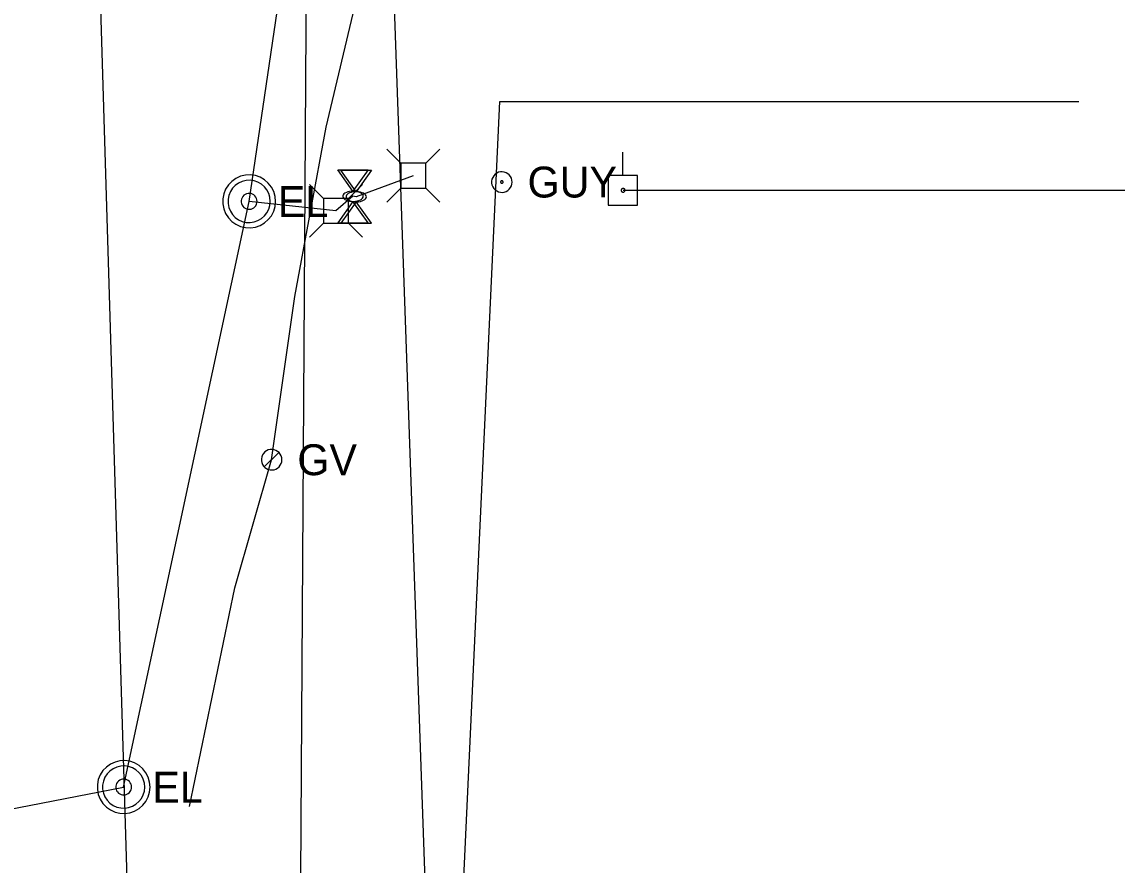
# Model space of a CAD drawing. Extents: x 596028 to 606371, y 330010 to 403088.
# Drawn here: x 605009.9 to 605146.4, y 331475.9 to 331581 of the extents above; entities that cross this region are included whole.
import ezdxf

# ---------------------------------------------------------------- set-up
doc = ezdxf.new("R2010")
doc.units = 0
for name, color, linetype in [('E_UTL_E', 7, 'Continuous'), ('E_UTL_E_Bold', 7, 'Continuous'), ('E_UTL_E_UG', 7, 'Continuous'), ('E_UTL_EGuyWire', 7, 'Continuous'), ('E_UTL_EPowerPole', 7, 'Continuous'), ('E_UTL_G', 7, 'Continuous'), ('E_UTL_G_UG', 7, 'Continuous'), ('E_UTL_Overhead', 7, 'Continuous'), ('E_UTL_SAN_UG', 7, 'Continuous'), ('E_UTL_SAN_UG_MMSD', 7, 'Continuous'), ('E_UTL_W_UG', 7, 'Continuous')]:
    doc.layers.add(name, color=color, linetype=linetype)

msp = doc.modelspace()

# ---------------------------------------------------------------- linework, layer by layer
at = {"layer": 'E_UTL_E'}
for points in [[(605057.12, 331563.38), (605055.37, 331565.13)], [(605060.22, 331563.38), (605061.97, 331565.13)], [(605060.22, 331563.38), (605057.12, 331563.38)], [(605057.12, 331563.38), (605057.12, 331560.28)], [(605060.22, 331560.28), (605060.22, 331563.38)], [(605041.5, 331558.64), (605041.44, 331559.26), (605041.27, 331559.86), (605040.98, 331560.42), (605040.59, 331560.92), (605040.12, 331561.33), (605039.57, 331561.64), (605038.98, 331561.85), (605038.36, 331561.93), (605037.73, 331561.9), (605037.12, 331561.76), (605036.55, 331561.5), (605036.04, 331561.13), (605035.61, 331560.68), (605035.27, 331560.15), (605035.04, 331559.57), (605034.92, 331558.95), (605034.92, 331558.32), (605035.04, 331557.71), (605035.27, 331557.13), (605035.61, 331556.6), (605036.04, 331556.14), (605036.55, 331555.78), (605037.12, 331555.52), (605037.73, 331555.37), (605038.36, 331555.34), (605038.98, 331555.43), (605039.57, 331555.64), (605040.12, 331555.95), (605040.59, 331556.36), (605040.98, 331556.85), (605041.27, 331557.41), (605041.44, 331558.01), (605041.5, 331558.64)], [(605041.5, 331558.64), (605041.44, 331559.26), (605041.27, 331559.86), (605040.98, 331560.42), (605040.59, 331560.92), (605040.12, 331561.33), (605039.57, 331561.64), (605038.98, 331561.85), (605038.36, 331561.93), (605037.73, 331561.9), (605037.12, 331561.76), (605036.55, 331561.5), (605036.04, 331561.13), (605035.61, 331560.68), (605035.27, 331560.15), (605035.04, 331559.57), (605034.92, 331558.95), (605034.92, 331558.32), (605035.04, 331557.71), (605035.27, 331557.13), (605035.61, 331556.6), (605036.04, 331556.14), (605036.55, 331555.78), (605037.12, 331555.52), (605037.73, 331555.37), (605038.36, 331555.34), (605038.98, 331555.43), (605039.57, 331555.64), (605040.12, 331555.95), (605040.59, 331556.36), (605040.98, 331556.85), (605041.27, 331557.41), (605041.44, 331558.01), (605041.5, 331558.64)], [(605040.84, 331558.64), (605040.79, 331559.14), (605040.65, 331559.62), (605040.42, 331560.07), (605040.11, 331560.46), (605039.73, 331560.79), (605039.3, 331561.04), (605038.82, 331561.2), (605038.33, 331561.28), (605037.83, 331561.25), (605037.34, 331561.13), (605036.88, 331560.92), (605036.47, 331560.63), (605036.13, 331560.27), (605035.86, 331559.85), (605035.67, 331559.38), (605035.57, 331558.89), (605035.57, 331558.39), (605035.67, 331557.89), (605035.86, 331557.43), (605036.13, 331557.01), (605036.47, 331556.64), (605036.88, 331556.35), (605037.34, 331556.14), (605037.83, 331556.02), (605038.33, 331556), (605038.82, 331556.07), (605039.3, 331556.24), (605039.73, 331556.49), (605040.11, 331556.82), (605040.42, 331557.21), (605040.65, 331557.66), (605040.79, 331558.14), (605040.84, 331558.64)], [(605040.84, 331558.64), (605040.79, 331559.14), (605040.65, 331559.62), (605040.42, 331560.07), (605040.11, 331560.46), (605039.73, 331560.79), (605039.3, 331561.04), (605038.82, 331561.2), (605038.33, 331561.28), (605037.83, 331561.25), (605037.34, 331561.13), (605036.88, 331560.92), (605036.47, 331560.63), (605036.13, 331560.27), (605035.86, 331559.85), (605035.67, 331559.38), (605035.57, 331558.89), (605035.57, 331558.39), (605035.67, 331557.89), (605035.86, 331557.43), (605036.13, 331557.01), (605036.47, 331556.64), (605036.88, 331556.35), (605037.34, 331556.14), (605037.83, 331556.02), (605038.33, 331556), (605038.82, 331556.07), (605039.3, 331556.24), (605039.73, 331556.49), (605040.11, 331556.82), (605040.42, 331557.21), (605040.65, 331557.66), (605040.79, 331558.14), (605040.84, 331558.64)], [(605039.19, 331558.64), (605039.17, 331558.83), (605039.12, 331559.01), (605039.03, 331559.17), (605038.92, 331559.32), (605038.78, 331559.44), (605038.61, 331559.54), (605038.44, 331559.6), (605038.25, 331559.63), (605038.06, 331559.62), (605037.88, 331559.57), (605037.71, 331559.5), (605037.55, 331559.39), (605037.42, 331559.25), (605037.32, 331559.09), (605037.25, 331558.92), (605037.22, 331558.73), (605037.22, 331558.54), (605037.25, 331558.36), (605037.32, 331558.18), (605037.42, 331558.03), (605037.55, 331557.89), (605037.71, 331557.78), (605037.88, 331557.7), (605038.06, 331557.66), (605038.25, 331557.65), (605038.44, 331557.68), (605038.61, 331557.74), (605038.78, 331557.83), (605038.92, 331557.95), (605039.03, 331558.1), (605039.12, 331558.27), (605039.17, 331558.45), (605039.19, 331558.64)], [(605039.19, 331558.64), (605039.17, 331558.83), (605039.12, 331559.01), (605039.03, 331559.17), (605038.92, 331559.32), (605038.78, 331559.44), (605038.61, 331559.54), (605038.44, 331559.6), (605038.25, 331559.63), (605038.06, 331559.62), (605037.88, 331559.57), (605037.71, 331559.5), (605037.55, 331559.39), (605037.42, 331559.25), (605037.32, 331559.09), (605037.25, 331558.92), (605037.22, 331558.73), (605037.22, 331558.54), (605037.25, 331558.36), (605037.32, 331558.18), (605037.42, 331558.03), (605037.55, 331557.89), (605037.71, 331557.78), (605037.88, 331557.7), (605038.06, 331557.66), (605038.25, 331557.65), (605038.44, 331557.68), (605038.61, 331557.74), (605038.78, 331557.83), (605038.92, 331557.95), (605039.03, 331558.1), (605039.12, 331558.27), (605039.17, 331558.45), (605039.19, 331558.64)], [(605047.47, 331559.01), (605045.72, 331560.76)], [(605050.57, 331559.01), (605052.32, 331560.76)], [(605057.12, 331560.28), (605055.37, 331558.53)], [(605057.12, 331560.28), (605060.22, 331560.28)], [(605060.22, 331560.28), (605061.97, 331558.53)], [(605050.57, 331559.01), (605047.47, 331559.01)], [(605047.47, 331559.01), (605047.47, 331555.91)], [(605050.57, 331555.91), (605050.57, 331559.01)], [(605047.47, 331555.91), (605045.72, 331554.16)], [(605047.47, 331555.91), (605050.57, 331555.91)], [(605050.57, 331555.91), (605052.32, 331554.16)], [(605025.85, 331485.6), (605025.79, 331486.22), (605025.62, 331486.82), (605025.33, 331487.38), (605024.94, 331487.88), (605024.47, 331488.29), (605023.92, 331488.6), (605023.33, 331488.81), (605022.71, 331488.89), (605022.08, 331488.86), (605021.47, 331488.72), (605020.9, 331488.46), (605020.39, 331488.09), (605019.96, 331487.64), (605019.62, 331487.11), (605019.39, 331486.53), (605019.27, 331485.91), (605019.27, 331485.28), (605019.39, 331484.67), (605019.62, 331484.09), (605019.96, 331483.56), (605020.39, 331483.1), (605020.9, 331482.74), (605021.47, 331482.48), (605022.08, 331482.33), (605022.71, 331482.3), (605023.33, 331482.39), (605023.92, 331482.6), (605024.47, 331482.91), (605024.94, 331483.32), (605025.33, 331483.81), (605025.62, 331484.37), (605025.79, 331484.97), (605025.85, 331485.6)], [(605025.85, 331485.6), (605025.79, 331486.22), (605025.62, 331486.82), (605025.33, 331487.38), (605024.94, 331487.88), (605024.47, 331488.29), (605023.92, 331488.6), (605023.33, 331488.81), (605022.71, 331488.89), (605022.08, 331488.86), (605021.47, 331488.72), (605020.9, 331488.46), (605020.39, 331488.09), (605019.96, 331487.64), (605019.62, 331487.11), (605019.39, 331486.53), (605019.27, 331485.91), (605019.27, 331485.28), (605019.39, 331484.67), (605019.62, 331484.09), (605019.96, 331483.56), (605020.39, 331483.1), (605020.9, 331482.74), (605021.47, 331482.48), (605022.08, 331482.33), (605022.71, 331482.3), (605023.33, 331482.39), (605023.92, 331482.6), (605024.47, 331482.91), (605024.94, 331483.32), (605025.33, 331483.81), (605025.62, 331484.37), (605025.79, 331484.97), (605025.85, 331485.6)], [(605025.19, 331485.6), (605025.14, 331486.1), (605025, 331486.58), (605024.77, 331487.03), (605024.46, 331487.42), (605024.08, 331487.75), (605023.65, 331488), (605023.17, 331488.16), (605022.68, 331488.24), (605022.18, 331488.21), (605021.69, 331488.09), (605021.23, 331487.88), (605020.82, 331487.59), (605020.48, 331487.23), (605020.21, 331486.81), (605020.02, 331486.34), (605019.92, 331485.85), (605019.92, 331485.35), (605020.02, 331484.85), (605020.21, 331484.39), (605020.48, 331483.97), (605020.82, 331483.6), (605021.23, 331483.31), (605021.69, 331483.1), (605022.18, 331482.99), (605022.68, 331482.96), (605023.17, 331483.03), (605023.65, 331483.2), (605024.08, 331483.45), (605024.46, 331483.78), (605024.77, 331484.17), (605025, 331484.62), (605025.14, 331485.1), (605025.19, 331485.6)], [(605025.19, 331485.6), (605025.14, 331486.1), (605025, 331486.58), (605024.77, 331487.03), (605024.46, 331487.42), (605024.08, 331487.75), (605023.65, 331488), (605023.17, 331488.16), (605022.68, 331488.24), (605022.18, 331488.21), (605021.69, 331488.09), (605021.23, 331487.88), (605020.82, 331487.59), (605020.48, 331487.23), (605020.21, 331486.81), (605020.02, 331486.34), (605019.92, 331485.85), (605019.92, 331485.35), (605020.02, 331484.85), (605020.21, 331484.39), (605020.48, 331483.97), (605020.82, 331483.6), (605021.23, 331483.31), (605021.69, 331483.1), (605022.18, 331482.99), (605022.68, 331482.96), (605023.17, 331483.03), (605023.65, 331483.2), (605024.08, 331483.45), (605024.46, 331483.78), (605024.77, 331484.17), (605025, 331484.62), (605025.14, 331485.1), (605025.19, 331485.6)], [(605023.54, 331485.6), (605023.52, 331485.79), (605023.47, 331485.97), (605023.38, 331486.13), (605023.27, 331486.28), (605023.13, 331486.4), (605022.96, 331486.5), (605022.79, 331486.56), (605022.6, 331486.59), (605022.41, 331486.58), (605022.23, 331486.53), (605022.06, 331486.46), (605021.9, 331486.35), (605021.77, 331486.21), (605021.67, 331486.05), (605021.6, 331485.88), (605021.57, 331485.69), (605021.57, 331485.5), (605021.6, 331485.32), (605021.67, 331485.14), (605021.77, 331484.99), (605021.9, 331484.85), (605022.06, 331484.74), (605022.23, 331484.66), (605022.41, 331484.62), (605022.6, 331484.61), (605022.79, 331484.64), (605022.96, 331484.7), (605023.13, 331484.79), (605023.27, 331484.91), (605023.38, 331485.06), (605023.47, 331485.23), (605023.52, 331485.41), (605023.54, 331485.6)], [(605023.54, 331485.6), (605023.52, 331485.79), (605023.47, 331485.97), (605023.38, 331486.13), (605023.27, 331486.28), (605023.13, 331486.4), (605022.96, 331486.5), (605022.79, 331486.56), (605022.6, 331486.59), (605022.41, 331486.58), (605022.23, 331486.53), (605022.06, 331486.46), (605021.9, 331486.35), (605021.77, 331486.21), (605021.67, 331486.05), (605021.6, 331485.88), (605021.57, 331485.69), (605021.57, 331485.5), (605021.6, 331485.32), (605021.67, 331485.14), (605021.77, 331484.99), (605021.9, 331484.85), (605022.06, 331484.74), (605022.23, 331484.66), (605022.41, 331484.62), (605022.6, 331484.61), (605022.79, 331484.64), (605022.96, 331484.7), (605023.13, 331484.79), (605023.27, 331484.91), (605023.38, 331485.06), (605023.47, 331485.23), (605023.52, 331485.41), (605023.54, 331485.6)]]:
    msp.add_lwpolyline(points, dxfattribs=at)
at = {"layer": 'E_UTL_E_Bold'}
for points in [[(605049.24, 331562.58), (605053.06, 331562.58)], [(605051.15, 331559.91), (605049.24, 331562.58)], [(605049.64, 331562.51), (605053.46, 331562.51)], [(605051.55, 331559.84), (605049.64, 331562.51)], [(605053.06, 331562.58), (605051.15, 331559.91)], [(605053.46, 331562.51), (605051.55, 331559.84)], [(605052.42, 331559.28), (605052.4, 331559.4), (605052.33, 331559.51), (605052.22, 331559.62), (605052.07, 331559.72), (605051.89, 331559.79), (605051.68, 331559.85), (605051.45, 331559.89), (605051.21, 331559.91), (605050.97, 331559.91), (605050.73, 331559.88), (605050.51, 331559.83), (605050.32, 331559.76), (605050.15, 331559.67), (605050.02, 331559.57), (605049.93, 331559.46), (605049.89, 331559.34), (605049.89, 331559.22), (605049.93, 331559.1), (605050.02, 331558.99), (605050.15, 331558.88), (605050.32, 331558.8), (605050.51, 331558.73), (605050.73, 331558.68), (605050.97, 331558.65), (605051.21, 331558.64), (605051.45, 331558.66), (605051.68, 331558.7), (605051.89, 331558.76), (605052.07, 331558.84), (605052.22, 331558.93), (605052.33, 331559.04), (605052.4, 331559.16), (605052.42, 331559.28)], [(605052.82, 331559.21), (605052.8, 331559.33), (605052.73, 331559.44), (605052.62, 331559.55), (605052.47, 331559.65), (605052.29, 331559.72), (605052.08, 331559.78), (605051.85, 331559.82), (605051.61, 331559.84), (605051.37, 331559.84), (605051.13, 331559.81), (605050.91, 331559.76), (605050.72, 331559.69), (605050.55, 331559.6), (605050.42, 331559.5), (605050.33, 331559.39), (605050.29, 331559.27), (605050.29, 331559.15), (605050.33, 331559.03), (605050.42, 331558.92), (605050.55, 331558.81), (605050.72, 331558.73), (605050.91, 331558.66), (605051.13, 331558.61), (605051.37, 331558.58), (605051.61, 331558.57), (605051.85, 331558.59), (605052.08, 331558.63), (605052.29, 331558.69), (605052.47, 331558.77), (605052.62, 331558.86), (605052.73, 331558.97), (605052.8, 331559.09), (605052.82, 331559.21)], [(605051.15, 331558.64), (605049.24, 331555.98)], [(605051.55, 331558.57), (605049.64, 331555.91)], [(605053.06, 331555.98), (605051.15, 331558.64)], [(605053.46, 331555.91), (605051.55, 331558.57)], [(605049.24, 331555.98), (605053.06, 331555.98)], [(605049.64, 331555.91), (605053.46, 331555.91)]]:
    msp.add_lwpolyline(points, dxfattribs=at)
at = {"layer": 'E_UTL_E_UG'}
for points in [[(605038.2, 331558.64), (605053.97, 331665.58), (605054.16, 331675.48), (605057.33, 331710.76), (605063.33, 331779.39), (605064.89, 331811.56), (605066.7, 331922.92), (605066.28, 331973.16), (605065.35, 332014.58), (605064.76, 332065.68), (605063.4, 332175.3), (605062.74, 332212.21)], [(604870.57, 331033.54), (605033.08, 331252.35), (605033.08, 331392.8), (605061.51, 331399.86), (605069.48, 331571.07), (605141.68, 331571.07)], [(605058.67, 331561.83), (605051.55, 331559.21), (605051.15, 331559.28), (605049.02, 331557.46), (605038.2, 331558.64)], [(604983.14, 331477.94), (605022.55, 331485.6), (605038.2, 331558.64)]]:
    msp.add_lwpolyline(points, dxfattribs=at)
at = {"layer": 'E_UTL_EGuyWire'}
for points in [[(605070.99, 331561.05), (605070.97, 331561.29), (605070.9, 331561.52), (605070.79, 331561.74), (605070.64, 331561.93), (605070.45, 331562.09), (605070.24, 331562.21), (605070.01, 331562.29), (605069.77, 331562.33), (605069.53, 331562.32), (605069.29, 331562.26), (605069.07, 331562.16), (605068.87, 331562.02), (605068.7, 331561.84), (605068.57, 331561.63), (605068.48, 331561.41), (605068.43, 331561.17), (605068.43, 331560.92), (605068.48, 331560.69), (605068.57, 331560.46), (605068.7, 331560.25), (605068.87, 331560.08), (605069.07, 331559.94), (605069.29, 331559.83), (605069.53, 331559.78), (605069.77, 331559.76), (605070.01, 331559.8), (605070.24, 331559.88), (605070.45, 331560), (605070.64, 331560.16), (605070.79, 331560.35), (605070.9, 331560.57), (605070.97, 331560.8), (605070.99, 331561.05)], [(605069.87, 331561.05), (605069.87, 331561.08), (605069.86, 331561.11), (605069.84, 331561.13), (605069.83, 331561.16), (605069.8, 331561.18), (605069.78, 331561.19), (605069.75, 331561.2), (605069.72, 331561.21), (605069.69, 331561.21), (605069.66, 331561.2), (605069.63, 331561.19), (605069.6, 331561.17), (605069.58, 331561.15), (605069.57, 331561.12), (605069.56, 331561.09), (605069.55, 331561.06), (605069.55, 331561.03), (605069.56, 331561), (605069.57, 331560.97), (605069.58, 331560.95), (605069.6, 331560.93), (605069.63, 331560.91), (605069.66, 331560.9), (605069.69, 331560.89), (605069.72, 331560.89), (605069.75, 331560.89), (605069.78, 331560.9), (605069.8, 331560.92), (605069.83, 331560.94), (605069.84, 331560.96), (605069.86, 331560.99), (605069.87, 331561.02), (605069.87, 331561.05)]]:
    msp.add_lwpolyline(points, dxfattribs=at)
at = {"layer": 'E_UTL_EPowerPole'}
for points in [[(605084.81, 331561.86), (605084.81, 331564.77)], [(605086.65, 331561.86), (605082.96, 331561.86)], [(605082.96, 331561.86), (605082.96, 331558.17)], [(605086.65, 331558.17), (605086.65, 331561.86)], [(605085.08, 331560.02), (605085.07, 331560.06), (605085.06, 331560.11), (605085.04, 331560.15), (605085.01, 331560.18), (605084.98, 331560.21), (605084.94, 331560.23), (605084.9, 331560.25), (605084.85, 331560.25), (605084.81, 331560.25), (605084.76, 331560.24), (605084.72, 331560.22), (605084.68, 331560.2), (605084.65, 331560.16), (605084.63, 331560.13), (605084.61, 331560.08), (605084.6, 331560.04), (605084.6, 331559.99), (605084.61, 331559.95), (605084.63, 331559.91), (605084.65, 331559.87), (605084.68, 331559.84), (605084.72, 331559.81), (605084.76, 331559.79), (605084.81, 331559.78), (605084.85, 331559.78), (605084.9, 331559.78), (605084.94, 331559.8), (605084.98, 331559.82), (605085.01, 331559.85), (605085.04, 331559.89), (605085.06, 331559.93), (605085.07, 331559.97), (605085.08, 331560.02)], [(605082.96, 331558.17), (605086.65, 331558.17)]]:
    msp.add_lwpolyline(points, dxfattribs=at)
at = {"layer": 'E_UTL_G'}
for points in [[(605042.28, 331526.42), (605042.26, 331526.66), (605042.19, 331526.89), (605042.08, 331527.11), (605041.93, 331527.3), (605041.74, 331527.46), (605041.53, 331527.58), (605041.3, 331527.66), (605041.06, 331527.7), (605040.82, 331527.69), (605040.58, 331527.63), (605040.36, 331527.53), (605040.16, 331527.39), (605039.99, 331527.21), (605039.86, 331527.01), (605039.77, 331526.78), (605039.72, 331526.54), (605039.72, 331526.29), (605039.77, 331526.06), (605039.86, 331525.83), (605039.99, 331525.62), (605040.16, 331525.45), (605040.36, 331525.31), (605040.58, 331525.2), (605040.82, 331525.15), (605041.06, 331525.14), (605041.3, 331525.17), (605041.53, 331525.25), (605041.74, 331525.37), (605041.93, 331525.53), (605042.08, 331525.72), (605042.19, 331525.94), (605042.26, 331526.17), (605042.28, 331526.42)], [(605040.09, 331525.51), (605041.91, 331527.32)]]:
    msp.add_lwpolyline(points, dxfattribs=at)
at = {"layer": 'E_UTL_G_UG'}
msp.add_lwpolyline([(605030.78, 331483.16), (605036.41, 331510.46), (605041, 331526.42), (605043.91, 331546.77), (605047.79, 331567.91), (605052.35, 331587.01), (605059.28, 331633.75), (605064.76, 331677.5), (605068.49, 331707.7), (605074.22, 331781.45), (605075.46, 331809.71), (605078.06, 331885.79), (605077.96, 331921.74), (605077.56, 331972.3), (605077.08, 332012.55), (605076.17, 332068.78), (605075.45, 332099.34), (605075.08, 332165.21), (605074.66, 332210.44), (605074.75, 332235.8)], dxfattribs=at)
at = {"layer": 'E_UTL_Overhead'}
msp.add_lwpolyline([(605084.84, 331560.02), (605283.92, 331560.02)], dxfattribs=at)
at = {"layer": 'E_UTL_SAN_UG'}
msp.add_line((605060.52, 331462.84), (605048.95, 331795.33), dxfattribs=at)
at = {"layer": 'E_UTL_SAN_UG_MMSD'}
msp.add_line((605023.68, 331451.52), (605012.41, 331824.88), dxfattribs=at)
at = {"layer": 'E_UTL_W_UG'}
msp.add_lwpolyline([(604662.85, 330776.78), (604719.99, 330861.17), (604771.51, 330900.13), (604792.62, 330926.22), (604804.59, 330947.13), (605054.68, 331381.7), (605055.13, 331442.45), (605044.65, 331474.36), (605047.01, 331851.63), (605038.36, 332278.66), (605035.8, 332410.28), (605072.23, 332411.32), (605076.98, 332411.12), (605079.88, 332411.16)], dxfattribs=at)

# ---------------------------------------------------------------- texts
at = {"layer": 'E_UTL_E'}
for p in [(605041.77, 331556.69), (605041.77, 331556.69), (605026.12, 331483.65), (605026.12, 331483.65)]:
    msp.add_text('EL', height=3.849, dxfattribs=at).set_placement(p)
at = {"layer": 'E_UTL_EGuyWire'}
msp.add_text('GUY', height=3.85, dxfattribs=at).set_placement((605072.92, 331559.12))
at = {"layer": 'E_UTL_G'}
msp.add_text('GV', height=3.85, dxfattribs=at).set_placement((605044.21, 331524.49))

doc.saveas('drawing.dxf')
